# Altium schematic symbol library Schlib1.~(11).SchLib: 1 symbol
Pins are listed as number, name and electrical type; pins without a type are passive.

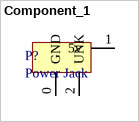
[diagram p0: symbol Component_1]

## Component_1
designator P?, comment Power Jack
footprint PCBComponent_1
pins: 0 GND (power), 1 5v, 2 UNK (power)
